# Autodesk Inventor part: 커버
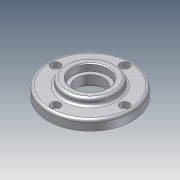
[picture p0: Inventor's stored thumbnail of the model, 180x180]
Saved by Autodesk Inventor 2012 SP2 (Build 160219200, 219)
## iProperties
Company: 한국ATC센터
Created: 2013-01
Part Number: 커버
Document SubType Name: Modeling
Designer: KYOUNG IL JANG
Density: 1 g/cm^3
Material: 기본값
Author: KYOUNG IL JANG
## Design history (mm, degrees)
sketch "스케치1"
  geometry: C1 r 31 at (0, 0) reference; C2 r 50 at (0, 0); 1 further point
  constraints: 1 centre point, 1 coincident
  dimensions: "d41" = 100 diameter of C2
extrude "돌출1" new body sketch "스케치1" distance "d0" = 12; taper "d1" = 0 deg
sketch "스케치2"
  geometry: C1 r 30 at (0, 0); 1 further point
  constraints: 1 centre point, 1 coincident
  dimensions: "d2" = 60 diameter of C1
extrude "돌출2" join sketch "스케치2" distance "d3" = 8; taper "d4" = 0 deg
fillet "모깎기1" dims "d5" = 3
sketch "스케치3" dims "d42" = 82
  geometry: 3 further points
  constraints: 2 vertical alignment, 1 coincident, 2 other
hole "구멍1" sketch "스케치3" at (0, 41) diameter "d6" = 6.6; stored, may be unused: countersink angle "d10" = 90 deg, drill point angle "d12" = 118 deg; dims "d7" = 6, "d8" = 11, "d9" = 6.5, "d11" = 8
hole "구멍2" diameter "d18" = 33; stored, may be unused: countersink angle "d22" = 90 deg, drill point angle "d24" = 118 deg; dims "d16" = 10, "d17" = 10, "d19" = 6, "d20" = 42, "d21" = 8.5, "d23" = 8
sketch "스케치4"
  geometry: C1 r 31 at (0, 0) reference; C2 r 22.5 at (0, 0); 1 further point
  constraints: 1 centre point, 1 coincident
  dimensions: "d43" = 45 diameter of C2
extrude "돌출3" join sketch "스케치4" distance "d25" = 6; taper "d26" = 0 deg
hole "구멍3" diameter "d29" = 50; stored, may be unused: countersink angle "d33" = 90 deg, drill point angle "d35" = 0 deg; dims "d27" = 10, "d28" = 10, "d30" = 6, "d31" = 42, "d32" = 8.5, "d34" = 7
fillet "모깎기2" dims "d36" = 3, "d37" = 0.3
chamfer "모따기1" distance "d38" = 1; stored, may be unused: second distance "d39" = 2, angle "d40" = 45 deg
node "솔리드1"
pattern_circular "원형 패턴1" dims angle "d14" = 360 deg
node "참조9"
node "참조11"
